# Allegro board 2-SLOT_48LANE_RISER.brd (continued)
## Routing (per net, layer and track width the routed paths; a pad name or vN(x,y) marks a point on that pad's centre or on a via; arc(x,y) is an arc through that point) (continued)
PE_SLOT2_TX_DP<0>: length 6.3
  BOTTOM w0.135: C39.2 279.99,83.95 279.99,83.55 280.14,83.4 280.14,82.99 279.99,82.84 279.99,82.44 280.14,82.28 280.14,81.88 279.99,81.73 279.99,79.81 280.13,79.67 280.28,79.59 280.46,79.65 J2.B14
PE_SLOT2_TX_DP<1>: length 6.4
  BOTTOM w0.135: C40.2 275.95,83.95 275.95,79.63 275.72,79.4 275.51,79.3 275.46,79.14 J2.B19
PE_SLOT2_TX_DP<2>: length 6.4
  BOTTOM w0.135: C41.2 272.04,83.98 272.04,79.76 271.68,79.4 271.52,79.32 271.46,79.14 J2.B23
PE_SLOT2_TX_DP<3>: length 6.4
  BOTTOM w0.135: J2.B27 267.46,79.14 267.51,79.31 267.69,79.4 267.97,79.68 267.97,83.95 C42.2
PE_SLOT2_TX_DP<4>: length 6.4
  BOTTOM w0.135: J2.B33 261.46,79.14 261.52,79.32 261.52,79.32 261.71,79.42 261.98,79.68 261.98,83.95 C103.2
PE_SLOT2_TX_DP<5>: length 6.4
  BOTTOM w0.135: J2.B37 257.46,79.14 257.52,79.33 257.76,79.45 257.99,79.68 257.99,84 C104.2
PE_SLOT2_TX_DP<6>: length 6.4
  BOTTOM w0.135: C105.2 253.98,83.95 253.98,79.67 253.72,79.41 253.51,79.31 253.46,79.14 J2.B41
PE_SLOT2_TX_DP<7>: length 6.4
  BOTTOM w0.135: C106.2 249.94,83.95 249.94,79.65 249.69,79.4 249.52,79.32 249.46,79.14 J2.B45
PE_SLOT2_TX_DP<8>: length 6.3
  BOTTOM w0.135: J2.B50 244.46,79.65 244.28,79.59 244.14,79.66 243.99,79.81 243.99,81.42 244.15,81.58 244.15,82.02 243.99,82.18 243.99,82.62 244.15,82.78 244.15,83.22 243.99,83.39 243.99,83.94 C107.2
PE_SLOT2_TX_DP<9>: length 6.3
  BOTTOM w0.135: J2.B54 240.46,79.65 240.28,79.59 240.14,79.66 239.99,79.81 239.99,81.42 240.15,81.58 240.15,82.02 239.99,82.18 239.99,82.62 240.15,82.78 240.15,83.22 239.99,83.39 239.99,83.94 C108.2
PE_SLOT2_TX_DP<10>: length 6.6
  BOTTOM w0.135: J2.B58 236.46,79.65 236.28,79.59 236.14,79.66 235.99,79.81 235.99,80.58 235.69,81.14 235.74,81.34 235.5,81.8 235.3,81.86 234.98,82.45 234.98,82.62 235.14,82.78 235.14,83.22 234.98,83.39 234.98,83.97 235.31,84.31 C109.2
PE_SLOT2_TX_DP<11>: length 6.3
  BOTTOM w0.135: J2.B62 232.46,79.65 232.28,79.59 232.14,79.66 231.99,79.81 231.99,81.42 232.15,81.58 232.15,82.02 231.99,82.18 231.99,82.62 232.15,82.78 232.15,83.22 231.99,83.39 231.99,83.94 C110.2
PE_SLOT2_TX_DP<12>: length 6.3
  BOTTOM w0.135: J2.B66 228.46,79.65 228.28,79.59 228.14,79.66 227.99,79.81 227.99,81.42 228.15,81.58 228.15,82.02 227.99,82.18 227.99,82.62 228.15,82.78 228.15,83.22 227.99,83.39 227.99,83.94 C111.2
PE_SLOT2_TX_DP<13>: length 6.3
  BOTTOM w0.135: C112.2 223.99,83.94 223.99,83.39 224.15,83.22 224.15,82.78 223.99,82.62 223.99,82.18 224.15,82.02 224.15,81.58 223.99,81.42 223.99,79.81 224.14,79.66 224.28,79.59 224.46,79.65 J2.B70
PE_SLOT2_TX_DP<14>: length 6.5
  BOTTOM w0.135: C113.2 219.23,83.94 219.23,83.39 219.39,83.22 219.39,82.78 219.23,82.62 219.23,82.27 219.37,82 219.57,81.94 219.82,81.46 219.76,81.26 219.87,81.06 219.99,80.62 219.99,79.81 220.14,79.66 220.28,79.59 220.46,79.65 J2.B74
PE_SLOT2_TX_DP<15>: length 6.3
  BOTTOM w0.135: J2.B78 216.46,79.65 216.28,79.59 216.14,79.66 215.99,79.81 215.99,81.42 216.15,81.58 216.15,82.02 215.99,82.18 215.99,82.62 216.15,82.78 216.15,83.22 215.99,83.39 215.99,83.94 C114.2
PE_WAKE_N: length 94.4
  TOP w0.114: v2(286.13,44.22) 286.13,43.76 R5.1 ; R6.1 v2(285.83,84.73)
  IN2 w0.147: v2(286.97,20.83) 286.97,27.3 290.3,30.63 290.3,30.71 291.72,32.13 291.72,33.86 290.91,34.67 290.91,38.1 289.69,39.32 289.69,41.1 287.57,43.22 287.14,43.22 v2(286.13,44.22) 285.24,45.11 285.24,47.45 287.96,50.16 287.96,62.92 286.79,64.08 286.79,72.59 287.73,73.53 287.73,74.42 288.94,75.63 288.94,78.8 287.75,80 287.75,82.82 v2(285.83,84.73)
  BOTTOM w0.114: v2(286.97,20.83) 283.67,17.53 283.67,13.72 284.56,12.83 284.56,11.23 286.56,9.22 286.56,6.58 285.83,5.84 J5.B11
PEX8747_SPARE0: length 3.9
  TOP w0.114: R93.2 v6(138.26,76.45) 137.67,76.45 137.61,76.51 v5(136.83,76.51)
  BOTTOM w0.114: v5(136.83,76.51) 136.83,76.82 136.49,77.16 U1.F1
PEX8747_SPARE1: length 3.8
  TOP w0.102: v7(124.15,76.26) 123.65,75.76 R74.2
  BOTTOM w0.114: U1.Y2 124.9,77.97 124.9,77 v7(124.15,76.26)
PEX8747_SPARE2: length 8.2
  TOP w0.102: R72.2 R73.1 125.68,76.33 v6(125.71,76.35) 126.27,76.91 126.27,78.64 126.9,79.27 126.9,80.78 127.27,81.16 v5(127.29,81.16)
  BOTTOM w0.114: U1.U6 v5(127.29,81.16)
PEX8747_SPARE3: length 3.8
  TOP w0.114: R75.1 v7(133.29,76.12)
  BOTTOM w0.114: U1.K2 133.19,78.36 132.9,78.07 132.9,77.31 132.86,77.27 132.86,76.55 v7(133.29,76.12)
PEX_EEP_CS_N: length 8.3
  TOP w0.114: R118.1 134.57,99.04 v6(134.57,97.54) 134.57,94.87 134.09,94.39 134.09,92.76 v5(133.69,92.36)
  BOTTOM w0.114: U1.K19 133.3,91.96 133.69,92.35 v5(133.69,92.36)
PEX_EEP_CS_R_N: length 4.9
  TOP w0.114: U6.1 v6(133.17,101.73) 133.17,100.48 R128.2 R118.2
PEX_EEP_HOLD_N: length 3
  TOP w0.114: U6.7 134.44,110.13 v2(133.83,110.74) 133.71,110.87 R129.2
PEX_EEP_SCLK: length 5.5
  TOP w0.114: v7(136.89,95.71) 136.89,96.96 137.24,97.31 v6(137.24,98.3) R130.2
  BOTTOM w0.114: U1.F22 136.51,94.36 136.89,94.73 v7(136.89,95.71)
PEX_EEP_SCLK_R: length 10.3
  TOP w0.114: U6.6 135.71,107.57 137.87,105.41 137.87,102.36 v6(137.49,101.98) 137.24,101.73 R130.1
PEX_EEP_SI: length 8.3
  TOP w0.114: R131.2 v6(138.25,96.8) 137.29,95.83 137.29,92.76 v5(136.89,92.36)
  BOTTOM w0.114: U1.F19 v5(136.89,92.36)
PEX_EEP_SI_R: length 9.8
  TOP w0.114: R131.1 138.51,100.6 138.51,106.93 v6(138.38,107.06) 136.98,108.46 U6.5
PEX_EEP_SO: length 10.4
  TOP w0.114: R119.1 131.01,98.42 v6(130.89,98.3) 130.08,97.49 130.08,92.99 129.85,92.76 129.49,92.76 129.29,92.56 129.29,91.41 129.69,91.01 v5(129.69,90.76)
  BOTTOM w0.114: U1.R18 v5(129.69,90.76)
PEX_EEP_SO_R: length 9.8
  TOP w0.114: U6.2 134.44,105.16 133.94,105.66 132.54,105.66 132.16,105.28 132.16,103.12 v6(132.03,103) 132.16,102.87 132.16,100.48 R121.2 R119.2
PEX_GPIO1: length 6
  TOP w0.102: v6(129.74,78.36) 130.15,78.76 v5(130.49,78.76)
  TOP w0.114: R44.1 R47.2 129.4,75.68 129.4,78.01 v6(129.74,78.36)
  BOTTOM w0.114: U1.N3 v5(130.49,78.76)
PEX_GPIO2: length 27.1
  TOP w0.102: 124.5,96.01 124.5,80.92 124.89,80.53 v5(124.89,80.36)
  TOP w0.114: R45.1 R48.2 v2(126.82,103.89) 126.82,98.53 124.5,96.2 124.5,96.01
  BOTTOM w0.114: U1.Y5 v5(124.89,80.36)
PEX_GPIO3: length 23.8
  TOP w0.114: R49.2 108.79,96.9 v2(108.54,96.65)
  IN1 w0.102: v5(126.49,85.96) 126.07,86.37 125.47,86.37 125.09,86.75 121.51,86.75 121.21,87.05 120.82,87.05 119.6,88.27 117.81,88.27
  IN1 w0.147: v2(108.54,96.65) 116.92,88.27 117.81,88.27
  BOTTOM w0.114: U1.V11 v5(126.49,85.96)
PEX_GPIO6: length 32.2
  TOP w0.114: v2(101.55,96.39) 101.42,96.52 R52.2
  IN1 w0.102: v5(124.89,81.16) 124.89,81.1 124.57,80.78 122.09,80.78 120.02,82.85 117.88,82.85 117.83,82.9 117.81,82.9
  IN1 w0.147: v2(101.55,96.39) 102.82,95.12 102.82,94.05 113.98,82.9 117.81,82.9
  BOTTOM w0.114: U1.Y6 v5(124.89,81.16)
PEX_GPIO7: length 7.2
  TOP w0.102: R53.2 131.4,75.71 131.4,77.82 131.27,77.94 v6(131.27,79.03) 131.7,79.46 131.7,80.94 131.92,81.16 v5(132.09,81.16)
  BOTTOM w0.114: U1.M6 v5(132.09,81.16)
PEX_GPIO10: length 34
  TOP w0.114: R56.2 100.41,96.27 v2(100.28,96.14)
  IN1 w0.102: 117.81,81.89 117.99,81.89 118.02,81.86 119.31,81.86 121.54,79.63 122.53,79.63 123.01,79.16 124.27,79.16 124.68,79.56 v5(124.89,79.56)
  IN1 w0.147: 117.81,81.89 114.07,81.89 100.28,95.67 v2(100.28,96.14)
  BOTTOM w0.114: U1.Y4 v5(124.89,79.56)
PEX_PERST_BUF_N: length 6.4
  TOP w0.114: U11.2 163.04,114.68 C154.1 163.99,115.16 C156.1 165.9,115.12 R351.2 166.85,114.17 Q2.D
PEX_PERST_N: length 70.1
  TOP w0.102: v5(126.49,81.96) 126.49,81.97 126.12,82.34 125.38,82.34 125.27,82.45 125.27,93.45 125.39,93.56 128.72,93.56 129.57,94.41 129.57,98.77
  TOP w0.114: U11.4 159.89,116.47 159.56,116.79 137.47,116.79 136.01,115.33 130.78,115.33 v2(130.63,115.19) ; v2(130.51,111.51) 130.51,111.38 129.57,110.44 129.57,102.92 v6(129.62,102.87) 129.57,102.82 129.57,98.77
  IN2 w0.147: v2(130.51,111.51) 130.51,115.06 v2(130.63,115.19)
  BOTTOM w0.114: U1.V7 v5(126.49,81.96)
PEX_RORT_GOOD0_N: length 4.4
  TOP w0.102: v5(139.29,77.96) 139.65,77.6 v6(139.65,77.22) 139.65,75.58 R46.2
  BOTTOM w0.114: U1.B3 139.29,78.76 v5(139.29,77.96)
PEX_RORT_GOOD4_N: length 3.5
  TOP w0.102: v6(127.89,76.3) 127.71,76.12 R50.2
  TOP w0.114: v5(128.09,77.96) 128.09,76.5 v6(127.89,76.3)
  BOTTOM w0.114: U1.T2 v5(128.09,77.96)
PEX_RORT_GOOD5_N: length 35.7
  TOP w0.114: R51.2 106.38,98.91 106.38,95.38 105.61,94.61 v2(103.84,94.61)
  IN1 w0.102: 117.81,83.97 118.14,83.64 120.19,83.64 120.93,82.91 122.12,82.91 122.69,82.34 125.05,82.34 125.29,82.1 125.29,81.56 v5(125.69,81.16)
  IN1 w0.147: v2(103.84,94.61) 104.73,93.73 104.73,93.47 114.23,83.97 117.81,83.97
  BOTTOM w0.114: U1.W6 v5(125.69,81.16)
PEX_RORT_GOOD8_N: length 4.7
  TOP w0.102: v6(127.26,77.75) 128.09,78.58 v5(128.09,78.76)
  TOP w0.114: R54.2 126.7,77.19 v6(127.26,77.75)
  BOTTOM w0.114: U1.T3 v5(128.09,78.76)
PEX_RORT_GOOD9_N: length 37
  TOP w0.114: R55.2 100.92,99.84 100.92,96.14 v2(102.06,95)
  IN1 w0.102: 117.81,82.19 118,82.19 118.11,82.08 119.4,82.08 121.5,79.98 125.12,79.98 125.5,80.36 v5(125.69,80.36)
  IN1 w0.147: v2(102.06,95) 102.06,94.32 114.19,82.19 117.81,82.19
  BOTTOM w0.114: U1.W5 v5(125.69,80.36)
PG_CKPWRGD_N: length 4.1
  TOP w0.114: R3.2 296.13,47.5 Q3.D v2(297.74,47.74) Q4.G
PG_MOS: length 3.5
  TOP w0.114: Q3.G 296.72,49.94 296.42,50.24 v2(296.42,50.83) 296.61,51.01 R298.2 R297.2
PST_PE_SLOT1_N: length 8.1
  TOP w0.114: U17.4 282.92,29.58 282.91,29.59 R353.2 282.55,30.21 282.3,30.45 282.3,31.46 285.83,34.99 J1.A11
PST_PE_SLOT2_N: length 8.1
  TOP w0.114: J2.A11 285.83,75.57 282.4,72.14 282.4,70.99 282.55,70.85 R352.2 282.91,70.37 282.92,70.36 U16.4
PU_EEP_WP_R_N: length 4
  TOP w0.114: R120.2 136.22,101.45 v2(135.82,101.85) 135.71,101.96 U6.3
PU_PCA9548_SC0: length 5.8
  TOP w0.114: R96.2 306.53,45.24 305.87,44.58 305.87,42.52 v2(305.56,42.21) 305.44,42.09 U2.5
PU_PCA9548_SC2: length 5.7
  TOP w0.114: R100.2 301.96,41.86 v2(302.38,41.44) 302.84,40.98 U2.9
PU_PCA9548_SC4: length 8.4
  TOP w0.114: R145.2 299.54,27.61 v2(299.01,28.14) 299.8,28.93 299.8,31.98 301.54,33.72 U2.14
PU_PCA9548_SD0: length 6
  TOP w0.114: U2.4 306.09,41.7 306.61,42.21 v2(306.61,43.97) 306.61,44.38 R95.2
PU_PCA9548_SD2: length 5.9
  TOP w0.114: U2.8 303.49,41.16 302.62,42.04 v2(302.62,43.13) 302.62,44.96 R99.2
PU_PCA9548_SD4: length 9
  TOP w0.114: U2.13 300.89,33.75 299.34,32.2 299.34,29.47 297.74,27.86 v2(297.74,27.79) 298.08,27.45 R144.2
PU_VOE1_N: length 1.7
  TOP w0.114: R7.2 304.7,60.1 v2(304.12,60.1) U9.19 303.09,60.1
PU_VOE4_N: length 1.9
  TOP w0.114: R8.2 296.6,60.1 v2(297.21,60.1) U9.32 298.34,60.1
PU_VOE5_N: length 1.9
  TOP w0.114: 298.34,57.7 U9.38 297.5,57.7 v2(297.28,57.91) 297.21,57.99 R77.2
RST_PE_SLOT_N: length 250.3
  TOP w0.114: v2(282.17,66.6) 282.27,66.7 U16.2 ; U17.2 282.27,26.06 v2(281.97,25.76) 285.15,22.57 285.15,11.01 286.72,9.45 286.72,6.6 285.83,5.71 J5.A11 ; Q1.G 170.09,102.53 191.52,81.1 194.49,81.1 195.28,81.89 195.28,84.56 197.13,86.41 204.83,86.41 215.6,97.18 258.86,97.18 v2(263.36,101.68)
  IN2 w0.147: v2(263.36,101.68) 265.05,101.68 277.19,89.53 283.19,89.53 284.91,87.81 284.91,84.48 285.7,83.69 285.7,79.76 286.72,78.74 286.72,75.18 283.29,71.75 283.29,69.6 282.17,68.48 v2(282.17,66.6) 282.17,66.22 287.48,60.9 287.48,50.68 284.63,47.83 284.63,43.64 285.52,42.75 286.79,42.75 287.83,41.71 287.83,38.96 288.93,37.87 288.93,34.77 289.87,33.83 289.87,31.47 289.51,31.11 285.07,31.11 281.97,28.02 v2(281.97,25.76)
RST_PEX_MOS_N: length 5.6
  TOP w0.114: R348.2 166.96,110.72 166.98,110.74 Q1.D 167.89,111.93 168.86,112.9 v2(168.86,113.22) Q2.G
SLOT1_JTAG_TCK: length 4.5
  TOP w0.114: J1.A5 291.83,31.61 R275.2
SLOT1_JTAG_TDI: length 2.5
  TOP w0.114: J1.A6 290.83,31.59 R262.2
SLOT1_JTAG_TDO: length 4.5
  TOP w0.114: J1.A7 289.83,31.58 R263.2
SLOT1_JTAG_TMS: length 2.5
  TOP w0.114: J1.A8 289.08,33.01 289.08,31.32 R264.2
SLOT1_JTAG_TRST_N: length 4.9
  TOP w0.114: J1.B9 287.83,42.62 R261.2
SLOT2_JTAG_TCK: length 4.6
  TOP w0.114: J2.A5 291.83,73.12 292.56,72.39 R260.2
SLOT2_JTAG_TDI: length 2.5
  TOP w0.114: J2.A6 290.83,73.36 291.54,72.64 R257.2
SLOT2_JTAG_TDO: length 4.5
  TOP w0.114: J2.A7 289.83,73.27 290.53,72.57 R258.2
SLOT2_JTAG_TMS: length 2.5
  TOP w0.114: J2.A8 288.83,73.2 289.51,72.52 R259.2
SLOT2_JTAG_TRST_N: length 4.8
  TOP w0.114: J2.B9 287.86,78.43 R252.2
STRAP_I2C_SMBUS_CFG_EN_N: length 38.3
  TOP w0.114: R113.2 99.9,99.04 99.9,97.9 R114.1 99.39,94.87 v2(100.03,94.23)
  IN1 w0.102: v5(124.89,78.76) 124.74,78.76 124.32,78.34 122.19,78.34 119.12,81.41 118.11,81.41 117.98,81.29 117.81,81.29
  IN1 w0.147: v2(100.03,94.23) 100.53,94.23 113.48,81.29 117.81,81.29
  BOTTOM w0.114: U1.Y3 v5(124.89,78.76)
STRAP_I2C_SMBUS_EN: length 8.3
  TOP w0.102: 136.25,79.17 136.63,79.56 v5(136.89,79.56) ; R111.2 R112.1
  TOP w0.109: 136.25,79.17 135.87,79.17 135.64,78.94 135.64,77.72 135.82,77.55 136.88,77.55 v6(136.93,77.5)
  TOP w0.114: v6(136.93,77.5) 136.93,77.22 136.35,76.63 136.35,75.63 136.22,75.5 R112.1
  BOTTOM w0.114: U1.F4 v5(136.89,79.56)
STRAP_PLL_BYPASS_N: length 17
  TOP w0.114: R117.2 125.3,105.05 125.3,100.46 v2(124.66,99.82)
  IN1 w0.102: 126.49,91.32 125.86,91.95 125.45,91.95 125.27,92.13 125.27,97.28 125.43,97.43 125.43,99.06 v2(124.66,99.82)
  IN1 w0.112: 126.49,91.32 v5(126.49,90.76)
  BOTTOM w0.114: U1.V17 v5(126.49,90.76)
STRAP_RESERVED0: length 13.9
  TOP w0.114: v2(124.79,98.42) 125.81,99.44 R70.2
  IN1 w0.102: v2(124.79,98.42) 124.47,98.1 124.47,93.8 124.47,93.8 124.47,92.32 125.23,91.56
  IN1 w0.112: 125.23,91.56 v5(125.69,91.56)
  BOTTOM w0.114: v5(125.69,91.56) 126.49,91.56 126.89,91.16 U1.V18
STRAP_RESERVED5: length 25.9
  TOP w0.114: R59.1 v2(103.46,96.52)
  IN1 w0.102: v5(122.49,83.56) 121.59,84.45 118.5,84.45 117.81,85.15
  IN1 w0.147: v2(103.46,96.52) 103.46,96.39 114.7,85.15 117.81,85.15
  BOTTOM w0.114: U1.AD9 v5(122.49,83.56)
STRAP_RESERVED7: length 2.4
  TOP w0.102: R61.1 133.79,78.78 v6(133.78,78.79) 133.78,78.97 133.69,79.06 v5(133.69,79.56)
  BOTTOM w0.114: U1.K3 133.29,79.16 v5(133.69,79.56)
STRAP_RESERVED9: length 3.1
  TOP w0.102: R65.1 139.82,92.9 v6(139.78,92.86) 139.78,92.77 139.67,92.66 139.67,91.94 v5(139.29,91.56)
  BOTTOM w0.114: U1.B18 v5(139.29,91.56)
STRAP_RESERVED14: length 23.6
  TOP w0.114: v2(107.9,95.5) 107.9,96.77 108.27,97.15 108.27,99.83 R69.2
  IN1 w0.102: v2(119.89,86.35) 118.84,87.4 117.81,87.4
  IN1 w0.147: v2(107.9,95.5) 116,87.4 117.81,87.4
  BOTTOM w0.114: U1.AD12 121.65,85.92 120.32,85.92 v2(119.89,86.35)
STRAP_RESERVED15: length 23.5
  TOP w0.114: R64.2 111.08,98.28 v2(111.08,95.63)
  IN1 w0.102: v5(125.69,87.56) 125.69,87.46 125.18,86.95 121.71,86.95 121.41,87.25 121.01,87.25 119.48,88.77
  IN1 w0.147: v2(111.08,95.63) 117.93,88.77 119.48,88.77
  BOTTOM w0.114: U1.W14 v5(125.69,87.56)
STRAP_RESERVED16: length 18
  TOP w0.114: v2(123.39,98.42) 123.39,98.55 124.03,99.19 124.03,100.2 124.79,100.97 R67.1
  IN1 w0.102: v5(126.49,88.36) 126.42,88.36 126.09,88.7 126.09,90.96 125.88,91.16 125.12,91.16 125.1,91.18 123.91,91.18 123.67,91.42 123.67,98.02 123.39,98.3 v2(123.39,98.42)
  BOTTOM w0.114: U1.V14 v5(126.49,88.36)
STRAP_RESERVED19: length 6.2
  TOP w0.102: 143.28,85.47 140.58,85.47 v5(140.09,85.96)
  TOP w0.114: R60.2 144.48,85.22 v6(143.97,85.72) 143.71,85.47 143.28,85.47
  BOTTOM w0.114: U1.B12 v5(140.09,85.96)
STRAP_RESERVED20: length 31.2
  TOP w0.114: R318.1 101.93,99.04 101.93,98.68 102.31,98.3 v2(102.31,97.54)
  IN1 w0.102: v5(122.49,81.16) 122.07,81.16 120.05,83.17 118.02,83.17 117.81,83.39
  IN1 w0.147: 117.81,83.39 114.23,83.39 103.2,94.41 103.2,95.38 102.31,96.27 v2(102.31,97.54)
  BOTTOM w0.114: U1.AD6 v5(122.49,81.16)
STRAP_RESERVED21: length 33
  TOP w0.114: R71.1 v2(98.38,96.52)
  IN1 w0.102: v5(122.49,78.76) 122.49,78.86 122.05,79.3 121.52,79.3 119.2,81.61 118.02,81.61 118,81.59 117.81,81.59
  IN1 w0.147: 117.81,81.59 113.72,81.59 100.29,95.01 99.89,95.01 v2(98.38,96.52)
  BOTTOM w0.381: U1.AD3 v5(122.49,78.76)
STRAP_STN1_PORTCFG0: length 12.1
  TOP w0.102: v5(135.29,84.36) 135.29,84.41 135.62,84.74 136.25,84.74 136.48,84.96 136.48,85.32 136.73,85.58 137.35,85.58 v6(137.75,85.98) 138.15,85.58 139.92,85.58 140.29,85.22 143.23,85.22 143.28,85.16
  TOP w0.114: R62.2 R63.1 143.28,85.16
  BOTTOM w0.114: U1.H10 v5(135.29,84.36)
STRAP_STN2_PORTCFG0: length 2.2
  TOP w0.102: v5(130.49,92.36) 130.5,92.35 R57.2 R58.1
  BOTTOM w0.114: U1.N19 v5(130.49,92.36)
STRAP_TESTMODE0: length 22.3
  TOP w0.114: R115.2 R116.1 121.11,102.13 v2(121.11,98.55)
  IN1 w0.102: 121.11,96.01 121.11,95.76 121.36,95.5 121.36,89.74 123.14,87.96 126.14,87.96 126.49,87.61 v5(126.49,87.56)
  IN1 w0.147: v2(121.11,98.55) 121.11,96.01
  BOTTOM w0.114: U1.V13 v5(126.49,87.56)
STRAP_UP_PORTSEL0: length 3.3
  TOP w0.102: R68.1 135.69,93.47 135.69,91.99 135.29,91.59 v5(135.29,91.56)
  BOTTOM w0.114: U1.H18 v5(135.29,91.56)
STRAP_UP_PORTSEL1: length 4.4
  TOP w0.102: R66.1 132.48,94.66 132.48,91.75 132.29,91.56 v5(132.09,91.56)
  BOTTOM w0.114: U1.M18 v5(132.09,91.56)
THER_SEN2_DN: length 332.5
  IN2 w0.254: v2(288.62,91.09) 288.34,90.81 286.49,90.81 284.33,92.96 277.96,92.96 265.72,105.21 210.37,105.21 206.61,108.97 192.64,108.97 184.79,116.81 66.52,116.81 27.43,77.73 27.43,63.58 26.75,62.89 26.04,62.89 v2(25.58,63.35)
  BOTTOM w0.254: v2(288.62,91.09) 288.9,90.81 291.8,90.81 303.67,78.93 304.57,78.93 304.7,79.07 U4.3 ; v2(25.58,63.35) 25.09,62.86 24.58,62.86 24.46,62.99 C260.2 23.43,63.54 Q25.2
THER_SEN2_DP: length 332.8
  IN2 w0.254: v2(25.58,62.05) 26.04,62.51 26.91,62.51 27.81,63.42 27.81,77.57 66.68,116.43 184.63,116.43 192.48,108.58 206.45,108.58 210.21,104.83 265.56,104.83 277.8,92.58 284.18,92.58 286.34,90.42 288.34,90.42 v2(288.62,90.14)
  BOTTOM w0.254: U4.2 304.7,78.41 304.57,78.55 303.51,78.55 291.64,90.42 288.9,90.42 v2(288.62,90.14) ; Q25.1 21.57,62.59 Q25.3 23.37,62.59 23.77,62.19 C260.1 24.46,62.19 24.67,62.4 25.24,62.4 v2(25.58,62.05)
THER_SEN_DN_1: length 130.1
  TOP w0.254: Q5.2 316.25,96.41 C468.2 v2(310.47,96.41) 310.26,96.2 216.95,96.2 205.89,85.14 197.86,85.14 196.7,83.98 196.7,81.58 197.51,80.77 198.18,80.77 198.24,80.71 U10.3
THER_SEN_DN_2: length 205.5
  TOP w0.254: U10.5 198.24,79.71 198.18,79.77 190.97,79.77 160.25,110.49 157.05,110.49 153.98,113.56 63.6,113.56 32.48,82.44 25.72,82.44 v2(25.27,81.99) 24.99,82.28 C469.2 24.06,82.11 Q6.2
THER_SEN_DP_1: length 129.4
  TOP w0.254: 311.67,95.82 v2(311.74,95.76) ; 311.67,95.82 217.11,95.82 206.05,84.76 198.02,84.76 197.08,83.82 197.08,81.74 197.67,81.15 198.18,81.15 198.24,81.21 U10.2 ; 311.67,95.82 312.45,95.82 312.65,95.61 C468.1 314.18,95.61 Q5.3 315.04,95.5 315.99,94.55 Q5.1
THER_SEN_DP_2: length 205.8
  TOP w0.254: U10.4 198.24,80.21 198.18,80.15 191.13,80.15 160.41,110.87 157.21,110.87 154.13,113.94 63.45,113.94 32.32,82.82 25.72,82.82 v2(25.27,83.26) 25.09,83.08 C469.1 24.21,83.06 Q6.3 22.58,83.06 21.63,84.01 Q6.1
TLA2024_P0V9: length 3.5
  TOP w0.305: 261.18,29.45 261.45,29.72 U3.4
  TOP w0.381: R148.2 C153.1 260.63,28.91 261.18,29.45
TLA2024_P1V8: length 3.6
  TOP w0.305: 261.29,28.75 261.62,29.08 U3.5
  TOP w0.381: R146.2 C152.1 260.43,27.89 261.29,28.75
TLA2024_P3V3: length 3.9
  TOP w0.254: R147.2 C180.1 v1(261.44,27.08) 261.44,27.94 261.95,28.45 U3.6
TP_A19: length 8.2
  TOP w0.114: v1(275.54,10.79) 276.81,9.53 276.81,6.6 275.83,5.62 J5.A19
TP_A32: length 9.9
  TOP w0.114: v1(261.37,12.55) 261.37,12.19 263.16,10.4 263.16,6.34 262.83,6.01 J5.A32
TP_A33: length 8.2
  TOP w0.114: J5.A33 261.83,5.87 262.89,6.93 262.89,9.19 v1(261.39,10.69)
TP_A50: length 8.2
  TOP w0.114: J5.A50 244.83,5.86 245.8,6.83 245.8,10.19 v1(245.01,10.97)
TP_B12: length 8.2
  BOTTOM w0.114: J5.B12 282.83,5.92 282.59,6.16 282.59,7.68 281.51,8.76 v6(281.51,11.18)
TP_B82: length 10.5
  BOTTOM w0.114: v6(210.64,12.57) 210.82,12.4 211.81,12.4 212.83,11.38 J5.B82
TP_PE_SLOT_TRST_N: length 11.8
  BOTTOM w0.114: J5.B9 v3(287.83,15.37)
UNNAMED_60_RES_I55_A: length 1.2
  TOP w0.254: U3.1 263.72,30.83 R135.1
VR_P0V9_BT: length 4.6
  TOP w0.508: v2(69.63,42.44) 69.63,43.45 v6(70.69,44.5) PC587.1
  BOTTOM w0.305: PU23.14 v2(69.63,42.44)
VR_P0V9_PVIN: length 21.3
  TOP w0.305: PR426.1 70.9,50.17 70.27,49.54 v5(70.27,49.28)
  IN2 w0.305: v5(70.27,49.28) 70.27,48.96 71.52,47.72 72.64,47.72 73.3,47.06 73.3,45.33 71.15,43.18 71.15,40.01 71.71,39.45 77.6,39.45 v2(78.18,40.03)
  vias: v2(71.83,42.39) v2(72.54,42.39) v2(73.51,43.34) v2(73.7,40.25) v2(74.44,40.25) v2(75.19,40.26) v2(79.04,39.97) v6(71.63,41)
VR_P0V9_SW: length 1.9
  TOP w0.381: PC587.2 70.76,47.3 70.94,47.27 71.7,46.52 v2(71.7,45.99)
VR_P1V8_BT: length 3.4
  TOP w0.254: PU19.14 82.78,108.98 v2(82.93,109.13)
  BOTTOM w0.305: PC546.1 83.78,108.71 v6(83.72,108.71) 83.34,108.71 v2(82.93,109.13)
VR_P1V8_PVIN: length 13.7
  IN2 w0.305: v2(87.32,110.27) 87.32,109.07 86.84,108.58 84.81,108.58 84.28,108.05 84.28,105.83 83.64,105.19 81.76,105.19 81.25,104.68 81.25,104.01 v2(81.27,104)
  BOTTOM w0.305: v2(81.27,104) 81.27,103.39 PR370.1 v6(79.33,103.12)
  vias: v2(84.76,109.18) v2(85.52,109.18) v2(88.01,108.13)
VR_P1V8_SW: length 1.8
  BOTTOM w0.305: PC546.2 85.38,106.11 86.21,106.93 v2(86.34,106.93)
VR_P3V3_BT: length 3.6
  TOP w0.508: PC514.1 295.36,108.06 v1(295.58,108.29) 295.96,108.66 v2(296.5,108.66)
  BOTTOM w0.254: v2(296.5,108.66) 296.41,108.58 PU17.14
VR_P3V3_PVIN: length 24
  TOP w0.381: v2(298.33,99.31) PR341.1
  IN2 w0.305: v2(287.76,111.51) 293.76,111.51 294.98,110.29 294.98,108.26 292.94,106.22 292.94,104.19 295.08,102.05 295.08,101.14 296.4,99.82 297.82,99.82 v2(298.33,99.31)
  vias: v2(287,111.51) v2(288.53,110.97) v2(289.54,112.14) v2(291.14,110.97) v2(291.14,109.96) v2(291.65,110.47) v2(292.31,110.47) v2(292.7,107.67) v2(293.75,108.86) v2(294.37,108.54)
VR_P3V3_SW: length 3.4
  TOP w0.508: PC514.2 295.36,104.29 v1(295.11,104.04) 294.86,104.04 294.44,104.46 v2(294.44,105.54)

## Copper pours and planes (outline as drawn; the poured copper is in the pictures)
GND on TOP (solid shape): 15.11,91.21 15.11,89.99 14.99,89.87 12.98,89.87 12.83,90.02 12.83,91.01 13.18,91.36 14.96,91.36
GND on TOP (solid shape): 97.64,110.36 97.64,108.84 97.39,108.58 95.23,108.58 95.1,108.71 95.1,110.36 95.61,110.87 97.13,110.87
GND on TOP (solid shape): 98.96,103.86 98.96,102.77 98.76,102.57 95.61,102.57 95.23,102.95 95.23,103.86 95.35,103.99 98.83,103.99
GND on TOP (solid shape): 99.39,64.14 99.39,56.9 99.01,56.52 97.36,56.52 97.23,56.64 97.23,64.52 97.36,64.64 98.88,64.64
GND on TOP (solid shape): 160.35,108.08 160.35,99.06 159.84,98.55 153.24,98.55 152.22,99.57 152.22,104.14 156.8,108.71 159.72,108.71
GND on TOP (solid shape): 293.35,84.33 293.35,82.91 293.14,82.7 291.39,82.7 291.16,82.93 291.16,84.2 291.42,84.45 293.22,84.45
GND on TOP (solid shape): 293.35,43.69 293.35,42.27 293.14,42.06 291.39,42.06 291.16,42.29 291.16,43.56 291.42,43.81 293.22,43.81
GND on TOP (solid shape): 82.98,111.16 82.98,109.76 82.81,109.76 82.65,109.6 81.13,109.6 81.07,109.66 81.07,111.16 81.2,111.29 82.85,111.29
GND on TOP (solid shape): 15.32,103.12 15.32,101.98 15.19,101.85 13.03,101.85 12.78,102.11 12.78,103 13.03,103.25 14.43,103.25 14.43,103.25 15.19,103.25
GND on TOP (solid shape): 298.99,110.85 298.99,109.04 298.84,108.89 297.19,108.89 297.03,109.05 297.03,111.05 297.14,111.15 298.69,111.15
GND on TOP (solid shape): 15.19,97.54 15.19,96.39 15.06,96.27 13.03,96.27 12.78,96.52 12.78,97.43 12.99,97.64 13.01,97.66 13.04,97.66 15.06,97.66
GND on TOP (solid shape): 86.08,105.14 86.08,104.27 85.7,103.88 83.88,103.88 83.69,104.07 83.69,104.47 83.69,105.37 83.72,105.39 85.83,105.39
GND on TOP (solid shape): 69.17,42.09 69.17,41.41 71.45,39.13 72.72,39.13 72.85,39.01 72.85,38.13 72.65,37.93 68.43,37.93 67.28,39.08 67.28,42.74 67.34,42.8 68.46,42.8
GND on TOP (solid shape): 288.62,30.48 288.75,30.35 288.75,29.46 288.05,28.77 287.03,28.77 286.34,28.07 284.18,28.07 283.9,28.35 283.9,30.3 284.08,30.48 284.48,30.48
GND on TOP (solid shape): 288.88,70.99 288.88,69.95 288.62,69.7 287.73,69.7 287.1,69.06 283.95,69.06 283.8,69.22 283.8,70.87 283.92,70.99 286.97,70.99 287.1,71.12 288.75,71.12
GND on TOP (solid shape): 78.67,50.57 78.67,41.66 78.24,41.23 75.66,41.23 75.22,41.67 75.22,42.92 75.85,43.55 75.85,45.32 75.4,45.76 74.49,45.76 73.25,47.01 72.05,47.01 71.01,48.05 71.01,49.42 71.48,49.89 72.29,49.89 73.48,51.08 78.16,51.08
GND on TOP (solid shape): 276.18,108.3 276.18,100.14 276.16,100.08 276.1,100.06 274.8,100.06 274.65,100.21 274.65,102.21 274.79,102.35 274.79,102.36 274.86,102.44 274.86,104.42 274.65,104.64 274.65,108.09 274.89,108.33 275.68,108.33 275.69,108.34 276.14,108.34
GND on TOP (solid shape): 297.68,30.51 297.68,29.2 297.59,29.11 295.33,29.11 295.1,29.34 295.02,29.34 294.13,29.34 294.13,29.34 292.3,29.34 292.05,29.59 292.05,30.35 292.18,30.48 293.09,30.48 293.25,30.48 293.38,30.62 297.58,30.62
GND on TOP (solid shape): 282.05,112.9 282.05,110.74 282.68,110.12 284.78,110.12 286.06,108.84 288.33,108.84 289.19,109.69 290.41,109.69 291,109.1 291,108.09 290.37,107.46 290.37,105.69 290.81,105.24 291.73,105.24 292.97,104 294.16,104 295.21,102.96 295.21,101.58 294.48,100.86 293.96,100.86 293.81,100.71 291.83,100.71 291.83,100.71 282.43,100.71 281.39,101.75 281.39,107.17 281.12,107.44 280.17,107.44 280.07,107.54 280.07,113.18 280.19,113.31 281.65,113.31
GND on TOP (solid shape): 92.83,109.94 92.83,109.38 92.78,109.33 92.05,109.33 92,109.28 92,108.15 92,108.03 91.84,107.88 90.95,107.88 90.68,108.16 90.68,108.36 90.68,108.37 90.7,108.52 90.68,108.67 90.68,108.68 90.68,109.02 90.68,109.03 90.7,109.18 90.68,109.33 90.68,109.34 90.68,109.68 90.68,109.69 90.7,109.84 90.68,109.99 90.68,110 90.68,110.27 90.88,110.47 92.3,110.47
GND on TOP (solid shape): 282.36,7.45 283.26,9.11 285.14,9.25 286.12,8.26 286.18,8.12 286.23,7.97 286.31,7.88 286.31,6.79 285.95,6.43 285.9,6.43 285.79,6.54 285.79,7.45 284.33,8.92 282.87,7.45 282.87,1.5 282.85,1.45 282.79,1.43 282.58,1.43 282.54,1.45 282.51,1.5 282.51,5.95 282.43,5.95 282.38,5.97 282.36,6.02
GND on TOP (solid shape): outline of 172 points within 0.59,108 11,117.73
GND on TOP (solid shape): 320.78,117.74 321.32,117.51 321.54,116.97 321.54,9.68 321.32,9.14 320.78,8.92 297.74,8.92 296.52,8.43 295.96,7.24 295.96,7.21 295.89,7.14 295.61,7.14 295.5,7.19 295.46,7.3 296.18,8.81 297.74,9.42 320.78,9.42 320.96,9.5 321.03,9.68 321.03,116.97 320.96,117.15 320.78,117.23 2,117.23 1.3,116.94 1.02,116.24 1.02,34.44 1.03,34.28 1.05,34.15 1.09,34.03 1.15,33.92 1.24,33.79 1.3,33.71 1.38,33.64 1.51,33.56 1.62,33.5 1.75,33.46 1.87,33.43 2.03,33.42 29.75,33.42 29.91,33.31 30.08,33.2 30.15,33.03 30,32.92 2.02,32.92 1.81,32.93 1.61,32.97 1.43,33.03 1.25,33.12 1.08,33.23 0.95,33.35 0.83,33.49 0.71,33.66 0.62,33.84 0.56,34.02 0.52,34.21 0.51,34.42 0.51,116.24 0.94,117.3 2,117.74
GND on TOP (solid shape): outline of 343 points within 28,32.9 43,42.9
GND on TOP (solid shape): outline of 343 points within 128,32.9 143,42.9
GND on TOP (solid shape): outline of 343 points within 172.05,105 187.05,115
GND on TOP (solid shape): outline of 343 points within 305.25,62.77 320.25,72.77
GND on TOP (solid shape): outline of 343 points within 305.25,102 320.25,112
GND on TOP (solid shape): outline of 343 points within 305.25,11.41 320.25,21.41
GND on TOP (solid shape): outline of 370 points within 140.84,1.43 213.18,33.42
GND on BOTTOM (solid shape): 74.67,39.11 74.67,37.99 74.54,37.86 72.51,37.86 72.28,38.09 72.28,38.96 72.51,39.18 74.59,39.18
GND on BOTTOM (solid shape): 83.06,111.23 83.06,109.71 82.89,109.54 81.19,109.54 81.07,109.66 81.07,111.21 81.18,111.31 82.98,111.31
GND on BOTTOM (solid shape): 97.26,110.36 97.26,108.84 97,108.58 94.85,108.58 94.72,108.71 94.72,110.36 95.23,110.87 96.75,110.87
GND on BOTTOM (solid shape): 98.38,41.15 98.38,38.1 97.99,37.72 90.63,37.72 90.37,37.97 90.37,40.89 90.88,41.4 98.12,41.4
GND on BOTTOM (solid shape): 98.58,103.86 98.58,102.77 98.38,102.57 94.64,102.57 94.41,102.79 94.41,103.61 94.79,103.99 98.45,103.99
GND on BOTTOM (solid shape): 99.37,64.14 99.37,49.17 98.78,48.59 97.46,48.59 97.23,48.82 97.23,64.52 97.36,64.64 98.86,64.64
GND on BOTTOM (solid shape): 293.94,112.91 293.94,112.05 293.71,111.82 291.62,111.82 291.55,111.9 291.55,113.01 291.67,113.14 293.71,113.14
GND on BOTTOM (solid shape): 69.23,41.84 69.23,38.14 69,37.91 67.3,37.91 67.23,37.99 67.23,41.44 67.84,42.05 68.8,42.05 68.81,42.06 69.01,42.06
GND on BOTTOM (solid shape): 90.91,77.46 90.91,69.22 90.15,68.45 86.72,68.45 86.08,69.09 86.08,75.51 86.09,75.52 86.09,76.58 87.28,77.76 90.6,77.76
GND on BOTTOM (solid shape): 298.99,113.01 298.99,109.43 298.51,108.95 297.41,108.95 297.41,108.94 297.21,108.94 296.98,109.17 296.98,112.86 297.21,113.09 298.91,113.09
GND on BOTTOM (solid shape): 83.64,61.72 83.64,61.21 83.39,60.96 83.39,57.02 80.85,54.48 80.85,52.45 80.47,52.07 75.77,52.07 75.01,52.83 75.01,60.71 76.15,61.85 83.52,61.85
GND on BOTTOM (solid shape): 288.88,113.57 288.88,112.34 288.68,112.14 287.03,112.14 287,112.17 287,112.52 286.75,112.78 286.24,112.78 286.11,112.9 286.11,113.41 286.49,113.79 288.65,113.79
GND on BOTTOM (solid shape): 75.62,50.47 75.62,49.91 75.63,49.9 75.63,49.06 74.96,48.39 74.43,48.39 73.49,47.46 70.59,47.46 70.58,47.47 70.58,48.73 71.57,49.73 72.13,49.73 73.1,50.7 75.39,50.7
GND on BOTTOM (solid shape): 281.41,113.28 281.92,113.28 282.05,113.16 282.05,110.49 282.15,110.39 282.15,109.6 282.02,109.47 281.46,109.47 280.35,110.59 280.35,112.33 279.95,112.73 279.48,112.73 279.41,112.8 279.41,113.27 279.43,113.29 281.41,113.29
GND on BOTTOM (solid shape): 303.66,61.27 303.66,56.02 303.39,55.75 298.35,55.75 297.77,56.34 297.77,61.19 298.22,61.65 303.29,61.65
GND on BOTTOM (solid shape): 79.21,38.83 79.21,38.62 79.43,38.4 81.12,38.4 81.26,38.27 81.27,38.27 81.37,38.17 81.52,38.16 81.78,38.16 81.81,38.14 81.81,37.35 81.71,37.25 79.67,37.25 79.67,37.25 77.95,37.25 77.91,37.29 77.91,38.81 77.98,38.88 79.16,38.88
GND on BOTTOM (solid shape): 93.32,110.24 93.32,104.57 92.31,103.55 84.79,103.55 84.36,103.97 84.36,104.36 85.42,105.42 85.72,105.42 85.72,105.42 85.9,105.42 85.91,105.43 86.2,105.43 87.64,106.86 89.57,106.86 91.54,108.84 91.54,110.49 91.8,110.74 92.81,110.74
GND on BOTTOM (solid shape): 295.53,104.34 295.53,103.78 295.66,103.65 295.66,102.13 294.39,100.86 293.67,100.86 293.51,100.7 290.99,100.7 290.58,101.1 290.58,101.94 291.26,102.61 291.62,102.61 291.62,102.62 291.72,102.62 292.4,103.3 292.67,103.57 293.37,104.27 293.37,104.27 293.5,104.39 295.48,104.39
GND on BOTTOM (solid shape): 276.26,108.23 276.26,106.63 276.23,106.46 276.25,106.31 276.26,106.3 276.26,104.4 276.23,104.22 276.25,104.08 276.26,104.07 276.26,102.16 276.23,101.99 276.25,101.84 276.26,101.83 276.26,101.34 275.97,101.05 274.86,101.05 274.65,101.26 274.65,102.21 274.86,102.43 274.86,104.42 274.65,104.64 274.65,108.06 274.65,108.08 274.67,108.11 274.89,108.33 274.9,108.34 276.14,108.34
GND on BOTTOM (solid shape): 282.59,8.38 283.75,9.34 285.25,9.19 286.25,8.2 286.25,6.77 286.21,6.73 285.88,6.73 285.79,6.82 285.79,7.45 285.74,7.82 285.61,8.15 285.61,8.16 284.26,8.91 282.99,8.03 282.87,7.94 282.74,7.98 282.59,8.13
GND on BOTTOM (solid shape): outline of 108 points within 140.85,9.56 212.51,33.42
GND on BOTTOM (solid shape): 320.78,117.74 321.32,117.51 321.54,116.97 321.54,9.68 321.32,9.14 320.78,8.92 297.74,8.92 296.52,8.43 295.96,7.24 295.96,7.21 295.89,7.14 295.61,7.14 295.5,7.19 295.46,7.3 296.18,8.81 297.74,9.42 320.78,9.42 320.96,9.5 321.03,9.68 321.03,116.97 320.96,117.15 320.78,117.23 2,117.23 1.3,116.94 1.02,116.24 1.02,34.44 1.03,34.28 1.05,34.15 1.09,34.03 1.15,33.92 1.24,33.79 1.3,33.71 1.38,33.64 1.51,33.56 1.62,33.5 1.75,33.46 1.87,33.43 2.03,33.42 29.75,33.42 29.91,33.31 30.08,33.2 30.15,33.03 30,32.92 2.02,32.92 1.81,32.93 1.61,32.97 1.43,33.03 1.25,33.12 1.08,33.23 0.95,33.35 0.83,33.49 0.71,33.66 0.62,33.84 0.56,34.02 0.52,34.21 0.51,34.42 0.51,116.24 0.94,117.3 2,117.74
GND on BOTTOM (solid shape): outline of 343 points within 28,32.9 43,42.9
GND on BOTTOM (solid shape): outline of 343 points within 128,32.9 143,42.9
GND on BOTTOM (solid shape): outline of 343 points within 172.05,105 187.05,115
GND on BOTTOM (solid shape): outline of 343 points within 305.25,62.77 320.25,72.77
GND on BOTTOM (solid shape): outline of 343 points within 305.25,102 320.25,112
GND on BOTTOM (solid shape): outline of 343 points within 305.25,11.41 320.25,21.41
GND on GND (solid shape): outline of 8224 points within 0.51,5.69 321.54,117.74
GND on IN1 (solid shape): outline of 115 points within 140.85,5.66 213.18,33.42
GND on IN1 (solid shape): 320.78,117.74 321.32,117.51 321.54,116.97 321.54,9.68 321.32,9.14 320.78,8.92 297.74,8.92 296.48,8.39 295.96,7.14 295.96,5.69 295.45,5.69 295.45,7.14 296.12,8.75 297.74,9.42 320.78,9.42 320.96,9.5 321.03,9.68 321.03,116.97 320.96,117.15 320.78,117.23 2,117.23 1.3,116.94 1.02,116.24 1.02,34.44 1.03,34.28 1.05,34.15 1.09,34.03 1.15,33.92 1.24,33.79 1.3,33.71 1.38,33.64 1.51,33.56 1.62,33.5 1.75,33.46 1.87,33.43 2.03,33.42 29.75,33.42 29.91,33.31 30.08,33.2 30.15,33.03 30,32.92 2.02,32.92 1.81,32.93 1.61,32.97 1.43,33.03 1.25,33.12 1.08,33.23 0.95,33.35 0.83,33.49 0.71,33.66 0.62,33.84 0.56,34.02 0.52,34.21 0.51,34.42 0.51,116.24 0.94,117.3 2,117.74
GND on VCC1 (solid shape): outline of 10304 points within 1.02,5.69 321.03,117.23
GND on IN2 (solid shape): outline of 117 points within 140.85,5.69 213.18,33.42
GND on IN2 (solid shape): 320.78,117.74 321.32,117.51 321.54,116.97 321.54,9.68 321.32,9.14 320.78,8.92 297.74,8.92 296.48,8.39 295.96,7.14 295.96,5.69 295.45,5.69 295.45,7.14 296.12,8.75 297.74,9.42 320.78,9.42 320.96,9.5 321.03,9.68 321.03,116.97 320.96,117.15 320.78,117.23 2,117.23 1.3,116.94 1.02,116.24 1.02,34.44 1.03,34.28 1.05,34.15 1.09,34.03 1.15,33.92 1.24,33.79 1.3,33.71 1.38,33.64 1.51,33.56 1.62,33.5 1.75,33.46 1.87,33.43 2.03,33.42 29.75,33.42 29.91,33.31 30.08,33.2 30.15,33.03 30,32.92 2.02,32.92 1.81,32.93 1.61,32.97 1.43,33.03 1.25,33.12 1.08,33.23 0.95,33.35 0.83,33.49 0.71,33.66 0.62,33.84 0.56,34.02 0.52,34.21 0.51,34.42 0.51,116.24 0.94,117.3 2,117.74
GND on GND1 (solid shape): outline of 8351 points within 0.51,5.69 321.54,117.74
GND_L on IN1 (solid shape): outline of 383 points within -19.49,-9.03 -2.51,364.68
P0V9 on TOP (solid shape): 96.47,64.26 96.47,57.02 96.22,56.77 87.71,56.77 86.56,57.91 86.56,62.36 88.85,64.64 96.09,64.64
P0V9 on BOTTOM (solid shape): 96.34,64.01 96.34,49 97.59,47.75 98.25,47.75 99.01,46.99 99.01,43.18 98.88,43.05 83.9,43.05 82.75,44.2 82.75,55.24 84.28,56.77 84.28,61.21 84.15,61.34 84.15,61.8 84.25,61.9 84.74,61.9 84.79,61.85 85.55,61.85 86.06,62.36 86.06,63.88 86.82,64.64 95.71,64.64
P0V9 on VCC1 (solid shape): outline of 251 points within 82.88,57.66 142.57,101.09
P0V9_A on TOP (solid shape): 149.81,102.62 149.81,98.3 147.27,95.76 139.4,95.76 139.02,96.14 139.02,99.31 139.5,99.79 144.58,99.79 145.24,100.46 145.24,102.49 145.75,103 149.43,103
P0V9_A on BOTTOM (solid shape): 97.39,80.64 97.39,66.29 96.5,65.41 86.84,65.41 86.46,65.79 86.46,67.82 86.72,68.07 90.91,68.07 92.56,69.72 92.56,80.77 93.07,81.28 96.75,81.28
P0V9_A on VCC (solid shape): 97.45,103.44 97.47,103.38 97.49,103.33 97.52,103.29 97.56,103.25 97.61,103.21 97.66,103.18 97.71,103.16 97.77,103.15 97.82,103.15 97.88,103.15 97.93,103.17 97.99,103.19 98.03,103.22 98.08,103.25 98.13,103.3 98.16,103.3 98.19,103.3 98.21,103.3 98.27,103.25 98.31,103.22 98.36,103.19 98.41,103.17 98.47,103.15 98.52,103.15 98.58,103.15 98.64,103.16 98.69,103.18 98.74,103.21 98.78,103.24 98.82,103.29 98.85,103.33 98.88,103.38 98.9,103.44 98.91,103.5 144.5,103.5 145.24,102.76 145.24,75.04 127.86,57.66 87.07,57.66 87.07,58.4 82.88,62.59 82.88,65.77 83.14,65.77 83.14,65.45 83.36,65.23 84.03,65.23 84.05,65.21 84.36,65.21 84.59,65.43 84.59,65.74 84.34,65.99 83.36,65.99 83.14,65.77 82.88,65.77 82.88,82.32 89.87,89.3 89.87,99.34 94.04,103.5 97.43,103.5
P0V9_AGND on TOP (solid shape): 68.02,47.9 68.02,46.18 67.21,45.36 64.97,45.36 64.72,45.62 64.72,46.38 65.1,46.76 66.63,46.76 67.01,47.14 67.01,48.03 67.13,48.16 67.77,48.16
P0V9_AGND on BOTTOM (solid shape): 69.82,47.03 69.82,44.41 69.74,44.34 68.22,44.34 68.19,44.36 68.19,47.06 68.22,47.08 69.77,47.08
P1V8 on TOP (solid shape): 118.11,105.28 118.11,103 117.86,102.74 115.06,102.74 114.81,103 114.81,105.16 115.06,105.41 117.98,105.41
P1V8 on TOP (solid shape): 94.85,108.08 99.01,108.08 99.26,107.82 99.26,104.9 98.76,104.39 95.23,104.39 94.97,104.14 94.97,103 94.85,102.87 91.67,102.87 91.16,103.38 91.16,106.81 92.31,107.95 92.31,108.84 92.43,108.97 93.96,108.97
P1V8 on IN1 (solid shape): 105.38,95.82 105.38,95.88 105.44,95.9 105.53,95.86 115.43,85.99 115.44,85.93 115.39,85.9 115.3,85.9
P1V8 on IN1 (solid shape): 125.07,98.09 125.12,98 125.12,97.56 124.97,97.41 124.97,94.39 124.94,94.32 124.87,94.29 124.77,94.29 124.77,97.98 124.85,98.05 124.92,98.06 124.97,98.09
P1V8 on IN1 (solid shape): 122.56,82.04 122.86,82.04 122.93,82.01 122.96,81.94 123.31,81.63 123.62,81.98 123.62,82.04 123.76,82.04 123.76,81.98 124.09,81.63 124.42,81.98 124.42,82.04 124.56,82.04 124.56,81.98 124.66,81.72 124.93,81.63 124.99,81.63 124.99,81.49 124.93,81.49 124.69,81.43 124.56,81.21 124.56,81.2 124.47,81.11 124.42,81.16 124.42,81.18 124.07,81.49 123.76,81.14 123.76,81.08 123.62,81.08 123.62,81.14 123.29,81.49 122.96,81.14 122.96,81.08 122.82,81.08 122.82,81.14 122.68,81.43 122.37,81.47 122.36,81.46 122.19,81.46 121.23,82.43 121.21,82.54 121.3,82.6 122,82.6
P1V8 on IN1 (solid shape): outline of 16639 points within 93.42,48.39 147.27,107.11
P1V8_A on TOP (solid shape): 119.83,104.33 120.08,104.33 120.27,104.14 120.27,98.68 119.64,98.04 118.49,98.04 118.38,98.16 118.38,98.62 118.37,98.62 118.37,100.97 118.49,101.09 118.49,104.27 118.62,104.39 119.76,104.39
P1V8_A on IN2 (solid shape): outline of 9729 points within 111.84,80.77 135.84,105.03
P1V8_AGND on TOP (solid shape): 83.44,108.7 83.44,104.58 83.41,104.56 83.21,104.56 83.17,104.6 83.17,104.96 83.16,105.03 83.13,105.12 83.13,105.39 83.11,105.42 82.99,105.42 82.99,105.42 82.09,105.42 82.04,105.47 82.04,107.81 82.14,107.91 83.06,107.91 83.06,107.92 83.13,107.99 83.13,108.21 83.16,108.29 83.17,108.36 83.17,108.65 83.19,108.7 83.24,108.72 83.41,108.72
P1V8_AGND on BOTTOM (solid shape): 83.03,106.66 83.03,106.54 83.02,106.51 83.01,106.49 82.75,106.23 82.17,106.23 82.06,106.13 82.06,104.93 82.04,104.88 81.99,104.86 81.79,104.81 81.62,104.71 81.05,104.71 80.92,104.83 80.92,105.8 80.77,105.95 80.64,105.95 80.46,106.13 80.46,106.46 80.67,106.66 81.91,106.66 82.11,106.86 82.83,106.86
P3V3 on TOP (solid shape): 307.94,54.3 307.94,53.04 307.86,52.96 307.72,52.96 307.72,52.95 306.18,52.95 306.14,52.99 306.14,54.36 306.18,54.39 307.85,54.39
P3V3 on TOP (solid shape): 288.77,35.94 288.77,34.72 287.85,33.8 287.85,33.32 287.85,33.26 287.85,33.2 287.85,32.77 288.62,32 288.62,30.86 288.49,30.73 284.64,30.73 284.58,30.73 284.57,30.75 282.77,30.75 282.65,30.86 282.65,31.37 285.67,34.39 285.7,34.4 285.73,34.41 285.85,34.4 285.98,34.42 286.46,34.42 286.72,34.67 286.72,35.81 287.1,36.2 288.52,36.2
P3V3 on TOP (solid shape): 279.71,112.73 279.71,107.36 279.97,107.11 280.7,107.11 280.78,107.03 280.78,101.47 279.71,100.4 279.71,100.39 279.43,100.11 276.54,100.11 276.43,100.21 276.43,101.64 276.58,101.99 276.43,102.34 276.43,103.87 276.58,104.23 276.43,104.58 276.43,106.11 276.58,106.46 276.43,106.81 276.43,113.49 276.67,113.72 278.73,113.72
P3V3 on TOP (solid shape): 288.88,76.58 288.88,76.12 288.87,76.11 288.85,75.89 288.87,75.68 288.88,75.67 288.88,74.93 288.82,74.87 288.79,74.87 287.88,74.12 288.36,73.04 288.37,73.03 288.88,72.52 288.88,72.26 288.88,71.5 288.75,71.37 282.91,71.37 282.78,71.5 282.78,72.01 285.81,75.04 285.84,75.04 286.53,75.41 286.63,76.18 286.63,76.22 286.65,76.26 287.1,76.71 288.75,76.71
P3V3 on BOTTOM (solid shape): 279.1,113.51 279.1,112.55 279.26,112.39 279.56,112.39 279.9,112.05 279.9,111.85 279.91,111.83 279.91,110.56 281.12,109.36 281.12,107.78 281.26,107.65 282.41,107.65 282.48,107.57 282.48,102.8 281.28,101.61 280.82,101.61 279.64,100.42 277.4,100.42 277.39,100.42 276.7,100.42 276.67,100.43 276.65,100.45 276.51,100.58 276.51,101.74 276.52,101.76 276.58,101.99 276.52,102.22 276.51,102.24 276.51,103.98 276.52,103.99 276.58,104.23 276.52,104.46 276.51,104.48 276.51,106.21 276.52,106.23 276.58,106.46 276.52,106.69 276.51,106.71 276.51,113.61 276.61,113.72 278.9,113.72
P3V3 on VCC (solid shape): outline of 7413 points within 87.07,5.69 321.03,93.6
P3V3 on IN2 (solid shape): outline of 717 points within 62.82,47.5 108.66,87.38
P3V3 on IN2 (solid shape): outline of 3976 points within 276.3,45.59 309.83,113.16
P3V3_AGND on TOP (solid shape): 298.03,105.78 298.03,105.44 298.08,105.38 299.6,105.38 299.7,105.49 299.79,105.49 299.88,105.39 299.88,105.06 299.32,104.51 299.32,103.67 299.27,103.62 298.52,103.62 298.46,103.68 298.46,104.57 298.45,104.58 297.09,104.58 296.96,104.71 296.96,105.49 296.73,105.71 296.73,106.32 296.92,106.51 297.29,106.51
P3V3_AGND on BOTTOM (solid shape): 297.52,106.8 297.52,104.67 297.49,104.65 296.3,104.65 296.3,106.86 297.46,106.86
P3V3_BUF_VDDA on TOP (solid shape): 298.97,56.49 298.97,55.81 298.37,55.22 294.74,55.22 294.65,55.3 294.65,56.26 294.77,56.37 296.43,56.37 296.77,56.03 298.19,56.03 298.68,56.52 298.93,56.52
P3V3_BUF_VDDR on TOP (solid shape): 300.54,54.48 300.54,53.62 300.55,53.62 300.55,53.56 300.55,53.56 300.55,53.48 300.79,53.25 300.79,51.49 300.74,51.44 300.12,51.44 299.92,51.65 299.92,54.47 300,54.56 300.47,54.56
P3V3_CLK_BUF_VDD on TOP (solid shape): 304.74,56.8 304.74,56.1 305.1,55.73 305.1,54.81 305.43,54.48 305.43,52.45 305.26,52.28 304.39,52.28 304.25,52.42 304.25,56.21 304.21,56.26 304.21,56.82 304.27,56.87 304.67,56.87
P3V3_CLK_BUF_VDD on BOTTOM (solid shape): outline of 1449 points within 294.16,49.96 307.04,65.08
P3V3_MB on TOP (solid shape): 290.5,10.25 290.5,8.23 288.19,5.92 288.19,1.57 288.15,1.54 287.52,1.54 287.47,1.56 287.45,1.61 287.45,5.64 287.21,5.64 287.21,1.61 287.18,1.56 287.13,1.54 286.63,1.54 286.57,1.56 286.55,1.61 286.55,5.84 287.22,6.52 287.22,10 287.84,10.62 290.14,10.62
P3V3_MB on BOTTOM (solid shape): 290.51,10.68 290.51,8.37 289.38,7.24 289.38,6.17 289.18,5.97 289.18,1.52 289.08,1.43 288.54,1.43 288.47,1.5 288.47,5.99 288.14,6.33 288.14,10.82 288.49,11.18 290.02,11.18
P3V3_STBY_MB on TOP (solid shape): 286.84,83.46 286.93,83.46 287.22,83.46 287.33,83.36 287.33,82.63 287.52,82.44 287.52,81.35 287.52,81.34 287.52,79.79 287.35,79.63 286.36,79.63 286.16,79.83 286.16,82.47 286.41,82.73 286.41,83.41 286.46,83.46 286.76,83.46
P3V3_STBY_MB on TOP (solid shape): 286.84,42.94 286.93,42.95 287.2,42.95 287.31,42.84 287.31,41.9 287.48,41.73 287.48,39.37 287.22,39.12 286.36,39.12 286.16,39.32 286.16,41.73 286.34,41.91 286.34,42.17 286.34,42.88 286.41,42.95 286.76,42.95
P3V3_STBY_MB on BOTTOM (solid shape): 287.45,12.1 287.45,10.85 287.33,10.73 286.16,10.73 286.02,10.87 286.02,12.16 286.19,12.34 287.22,12.34
P3V3_STBY_MB on IN1 (solid shape): outline of 11136 points within 262.54,10.49 317.96,88.56
P12V on TOP (solid shape): 284.72,112.65 284.72,110.83 284.59,110.7 282.85,110.7 282.3,111.25 282.3,112.65 282.56,112.9 284.46,112.9
P12V on TOP (solid shape): 297.28,41.45 297.28,31.6 296.7,31.01 295.1,31.01 295,30.91 293.4,30.91 293.27,31.05 293.27,32.26 293.73,32.72 293.73,34.34 293.66,34.4 296.68,34.4 296.68,36.11 294.98,36.11 294.98,34.4 293.66,34.4 293.22,34.85 293.22,38.63 293.96,39.37 293.96,43.69 294.08,43.81 294.92,43.81
P12V on TOP (solid shape): 297.82,82.75 297.82,72.11 297.36,71.65 295.1,71.65 294.84,71.4 293.35,71.4 293.27,71.48 293.27,72.9 293.73,73.36 293.73,74.98 293.66,75.04 296.68,75.04 296.68,76.75 294.98,76.75 294.98,75.04 293.66,75.04 293.22,75.49 293.22,79.27 293.96,80.01 293.96,84.33 294.08,84.45 296.11,84.45
P12V on TOP (solid shape): outline of 627 points within 1.45,85.59 18.37,106.36
P12V on BOTTOM (solid shape): 91.16,109.98 91.16,108.97 90.15,107.95 88.88,107.95 88.62,108.2 88.62,110.24 88.75,110.36 90.78,110.36
P12V on BOTTOM (solid shape): 83.99,39.97 83.99,37.94 83.61,37.56 82.16,37.56 82.09,37.63 82.09,38.37 82.04,38.42 81.63,38.42 81.53,38.52 81.53,40.15 81.68,40.3 83.66,40.3
P12V on BOTTOM (solid shape): 285.86,113.67 285.86,113.03 285.73,112.9 285.37,112.9 284.87,112.4 284.87,111.08 284.65,110.87 282.68,110.87 282.3,111.25 282.3,113.41 282.68,113.79 285.73,113.79
P12V on IN1 (solid shape): outline of 6330 points within 1.6,72.01 303.23,116.2
P12V on VCC (solid shape): outline of 2878 points within 1.02,31.5 321.03,117.23
P12V_MB on TOP (solid shape): 294.77,9.65 294.77,6.22 295.19,5.8 295.19,1.51 295.15,1.47 294.52,1.47 294.47,1.5 294.45,1.55 294.45,5.64 294.21,5.64 294.21,1.55 294.19,1.5 294.13,1.47 293.55,1.47 293.5,1.5 293.47,1.55 293.47,5.89 292.86,6.5 292.86,9.81 292.92,9.87 294.55,9.87
P12V_MB on BOTTOM (solid shape): 294.9,9.62 294.9,8.23 295.15,7.98 295.15,5.84 295.2,5.79 295.2,1.52 295.13,1.45 295.1,1.43 295.07,1.43 294.52,1.43 294.47,1.45 294.45,1.5 294.45,5.64 294.21,5.64 294.21,1.5 294.19,1.45 294.14,1.43 293.53,1.43 293.48,1.45 293.46,1.5 293.46,5.9 293.45,5.9 293.45,6.25 292.86,6.83 292.86,9.8 292.93,9.87 294.66,9.87
P12V_PSU on TOP (solid shape): 10.96,88.94 11.54,88.36 12.36,88.39 15.06,88.39 15.32,88.14 15.32,87 15.19,86.87 14.22,86.87 14.22,86.79 14.17,86.74 14.17,85.93 13.72,85.47 8.59,85.47 7.7,86.36 7.7,89.66 8.21,90.17 9.73,90.17
P12V_PSU on IN2 (solid shape): 11.38,88.39 12.52,88.39 13.3,87.62 13.3,85.86 13.16,85.72 9.6,85.72 7.7,87.63 7.7,89.53 8.33,90.17 9.6,90.17
VR_P0V9_PVIN on TOP (solid shape): 74.36,45.2 75.18,45.2 75.42,44.96 75.42,43.72 74.79,43.1 74.79,41.47 75.47,40.79 79.45,40.79 79.58,40.67 79.58,39.27 79.33,39.01 74.12,39.01 73.68,39.45 71.81,39.45 71.05,40.21 71.85,40.21 71.85,40.15 71.86,40.1 71.88,40.05 71.91,40 71.94,39.95 71.98,39.91 72.03,39.88 72.08,39.86 72.13,39.84 72.19,39.83 72.24,39.83 72.3,39.83 72.35,39.85 72.4,39.87 72.45,39.9 72.49,39.93 72.53,39.97 72.56,40.02 72.59,40.07 72.6,40.13 72.61,40.18 72.61,40.24 72.6,40.29 72.59,40.34 72.56,40.4 72.53,40.44 72.49,40.48 72.45,40.52 72.4,40.55 72.35,40.57 72.3,40.58 72.24,40.59 72.19,40.59 72.13,40.58 72.08,40.56 72.03,40.53 71.98,40.5 71.94,40.46 71.91,40.42 71.88,40.37 71.86,40.32 71.85,40.26 71.85,40.21 71.05,40.21 70.24,41.03 70.24,41.97 70.26,42 70.31,42.07 70.34,42.15 70.37,42.23 70.39,42.31 70.4,42.39 70.4,42.44 70.4,42.74 70.4,42.77 70.42,42.79 70.44,42.81 70.47,42.82 71.37,42.82 71.92,43.38 71.92,44.73 72.85,45.65 73.92,45.65
VR_P0V9_PVIN on BOTTOM (solid shape): outline of 88 points within 69.69,37.5 80.76,44.52
VR_P0V9_SW on BOTTOM (solid shape): 78.58,47.64 78.58,43.76 78.5,43.68 74.49,43.68 74.29,43.89 74.29,44.68 74.06,44.91 73.21,44.91 73.19,44.92 70.2,44.92 70.17,44.95 70.17,46.98 70.19,47.04 70.25,47.06 74.03,47.06 74.34,47.36 74.34,47.79 74.39,47.85 78.37,47.85
VR_P1V8_PVIN on TOP (solid shape): 86.11,110.72 86.11,110.01 86.22,109.9 86.98,109.9 87.17,110.09 87.15,110.12 87.15,110.45 87.25,110.55 88.44,110.55 88.85,110.14 88.85,108.1 88.61,107.86 87.01,107.86 86.64,107.49 83.85,107.49 83.72,107.62 83.72,111.05 83.92,111.25 85.57,111.25
VR_P1V8_PVIN on BOTTOM (solid shape): 85.57,111.03 85.57,111.03 85.57,110.47 86.21,109.83 88.06,109.83 88.24,109.65 88.24,108.13 88.04,107.92 87.48,107.92 86.95,108.46 85.57,108.46 85.45,108.58 84.96,108.58 84,109.55 84,109.68 84.02,109.7 84.02,111.26 84.17,111.41 85.19,111.41
VR_P1V8_SW on TOP (solid shape): 87.99,107.19 88.49,107.19 88.88,106.81 88.88,102.74 88.75,102.62 86.72,102.62 86.46,102.87 86.46,105.28 86.03,105.71 83.76,105.71 83.73,105.74 83.7,105.76 83.7,107.1 83.79,107.19 87.99,107.19
VR_P3V3_PVIN on TOP (solid shape): outline of 85 points within 285.45,105.8 296.2,112.65
VR_P3V3_PVIN on BOTTOM (solid shape): outline of 86 points within 285.48,106.71 296.53,113.79
VR_P3V3_SW on BOTTOM (solid shape): 292.51,106.38 292.51,106.38 292.61,106.28 295.78,106.28 295.78,104.66 292.71,104.66 291.66,103.62 291.65,103.6 287.48,103.6 287.41,103.68 287.41,107.4 287.67,107.66 291.23,107.66

Small or netless copper shapes (teardrops, artwork), in the pictures only: 34 on TOP, 1 on BOTTOM, 1 on GND, 5 on IN1, 2 on VCC, 2 on VCC1, 2 on IN2, 1 on GND1

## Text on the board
Ref Des/Silkscreen Bottom: PWR_Conn | PCB-2RSMOXL8-P0 REV:P0
User.Comments: CR_PCIE_1 | CR_UNNAMED_1 | CR_P1V05_PCH_STBY_1 | CR_P3V3_1 | 2018/08/03 | Moxlie_2slot_riser | PCB-2RSMOXL8-P0
Ref Des/Silkscreen Top: C | D | J2 | Riser Slot2 (PLX PCIe P16) | J1 | Riser Slot1 (PLX PCIe P8) | PCB-2RSMOXL8-P0 REV:P0
User.25: FIGURE | SIZE | 10.0 | 16.0 | 22.0 | 24.0 | 28.0 | 41.0 | 44.0 | 174.0 | 221.0 | 47.0 | 95.0 | 119.0 | 158.0 | DRILL CHART: TOP to BOTTOM | ALL UNITS ARE IN MILS | TOLERANCE | +3.0/-3.0 | +4.0/-0.0 | +2.0/-2.0 | PLATED | NON-PLATED | QTY | 263 | 4157 | 28 | 80 | 30 | 4 | 820 | 76 | 2 | 10 | 6
